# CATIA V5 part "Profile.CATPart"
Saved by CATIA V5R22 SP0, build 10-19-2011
Part number: Profile
Material "Acier": density 7860 kg/m3, Young's modulus 2e+11 Pa, Poisson ratio 0.266, thermal expansion 1.17e-05 1/K
Bounding box of the stored display mesh (mm): x -10 to 10, y -10 to 10, z 0 to 1000
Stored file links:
  U:\S9A\PER\CAO\Assemblage\Cadre\Cadre_Metalique\Profile.CATPart
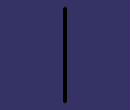
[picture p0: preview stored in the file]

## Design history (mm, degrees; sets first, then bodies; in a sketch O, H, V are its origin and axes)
Body1 (main body), material "Acier"
  Sketch1 on xy-plane, origin (0, 0, 0), H (1, 0, 0), V (0, 1, 0)
    line L1 (10, 10) -> (10, -10)
    line L2 (10, -10) -> (-10, -10)
    line L3 (-10, -10) -> (-10, 10)
    line L4 (-10, 10) -> (10, 10)
    length L2 = 20
    length L1 = 20
    vertical: L1 V, L3 V
    horizontal: L2 H, L4 H
    equidistance: L1 L3 O, L2 L4 O
  Pad1: profile Sketch1, direction (0, 0, 1), length 1000
  Sketch2 on end face of Pad1, origin (0, 0, 1000), H (1, 0, 0), V (0, 1, 0)
    line L1 (-4, -5) -> (4, -5)
    line L2 (4, -5) -> (4, -10)
    line L3 (4, -10) -> (-4, -10)
    line L4 (-4, -10) -> (-4, -5)
    reference projected line E1 (10, -10) -> (10, 10) from edge [face of Pad1 from Sketch1.L1 | end face of Pad1]
    reference projected line E2 (-10, -10) -> (10, -10) from edge [face of Pad1 from Sketch1.L2 | end face of Pad1]
    length L2 = 5
    length L3 = 8
    distance E1 L2 = 6
    horizontal: L1 H, L3 H
    vertical: L2 V, L4 V
    coincidence: L3 E2
  Pocket1: profile Sketch2, direction (0, 0, -1), length 1000
  CircPattern1: of Pocket1, instances 4, angular step 90, axis from end face of Pad1
  Chamfer1: length 1, angle 45, on edge [face of Pad1 from Sketch1.L1 | face of CircPattern1]; edge [face of CircPattern1 | face of Pad1 from Sketch1.L1]; edge [face of Pad1 from Sketch1.L4 | face of CircPattern1]; edge [face of CircPattern1 | face of Pad1 from Sketch1.L4]; edge [face of Pad1 from Sketch1.L3 | face of CircPattern1]; edge [face of CircPattern1 | face of Pad1 from Sketch1.L3]; edge [face of Pad1 from Sketch1.L2 | face of Pocket1 from Sketch2.L4]; edge [face of Pocket1 from Sketch2.L2 | face of Pad1 from Sketch1.L2]
  Sketch3 on face of Pocket1 from Sketch2.L1, origin (1.5953, -5, 963.9013), H (1, 0, 0), V (0, 0, 1)
    point P1 (-1.5953, -53.9013)
    reference projected line E1 (2.4047, 36.0987) -> (-5.5953, 36.0987) from edge [end face of Pad1 | face of Pocket1 from Sketch2.L1]
    reference projected line E2 (8.4047, -963.9013) -> (8.4047, 36.0987) from edge [face of Pad1 from Sketch1.L1 | face of Pad1 from Sketch1.L2]
    reference projected line E3 (-11.5953, -963.9013) -> (-11.5953, 36.0987) from edge [face of Pad1 from Sketch1.L2 | face of Pad1 from Sketch1.L3]
    distance E1 P1 = 90
    equidistance: E2 E3 P1
  Hole1: placed by Sketch3, at (0, -5, 910) direction (0, 1, 0), diameter 5, through (limit type 3)
  RectPattern1: of Hole1, direction 1 instances 1, spacing 37, along face of Pocket1 from Sketch2.L1, direction 2 instances 2, spacing 37, along face of Pocket1 from Sketch2.L1
  Sketch4 on face of Pocket1 from Sketch2.L1, origin (0.005, -5, 32.6213), H (1, 0, 0), V (0, 0, 1)
    point P1 (-0.005, 57.3787)
    reference projected line E1 (3.995, -32.6213) -> (-4.005, -32.6213) from edge [face of Pocket1 from Sketch2.L1 | start face of Pad1]
    reference projected line E2 (9.995, -32.6213) -> (9.995, 967.3787) from edge [face of Pad1 from Sketch1.L1 | face of Pad1 from Sketch1.L2]
    reference projected line E3 (-10.005, -32.6213) -> (-10.005, 967.3787) from edge [face of Pad1 from Sketch1.L2 | face of Pad1 from Sketch1.L3]
    distance E1 P1 = 90
    equidistance: E2 E3 P1
  Hole2: placed by Sketch4, at (0, -5, 90) direction (0, 1, 0), diameter 5, through (limit type 3)
  RectPattern2: of Hole2, direction 1 instances 1, spacing 37, along face of Pocket1 from Sketch2.L1, direction 2 instances 2, spacing 37, along face of Pocket1 from Sketch2.L1 reversed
